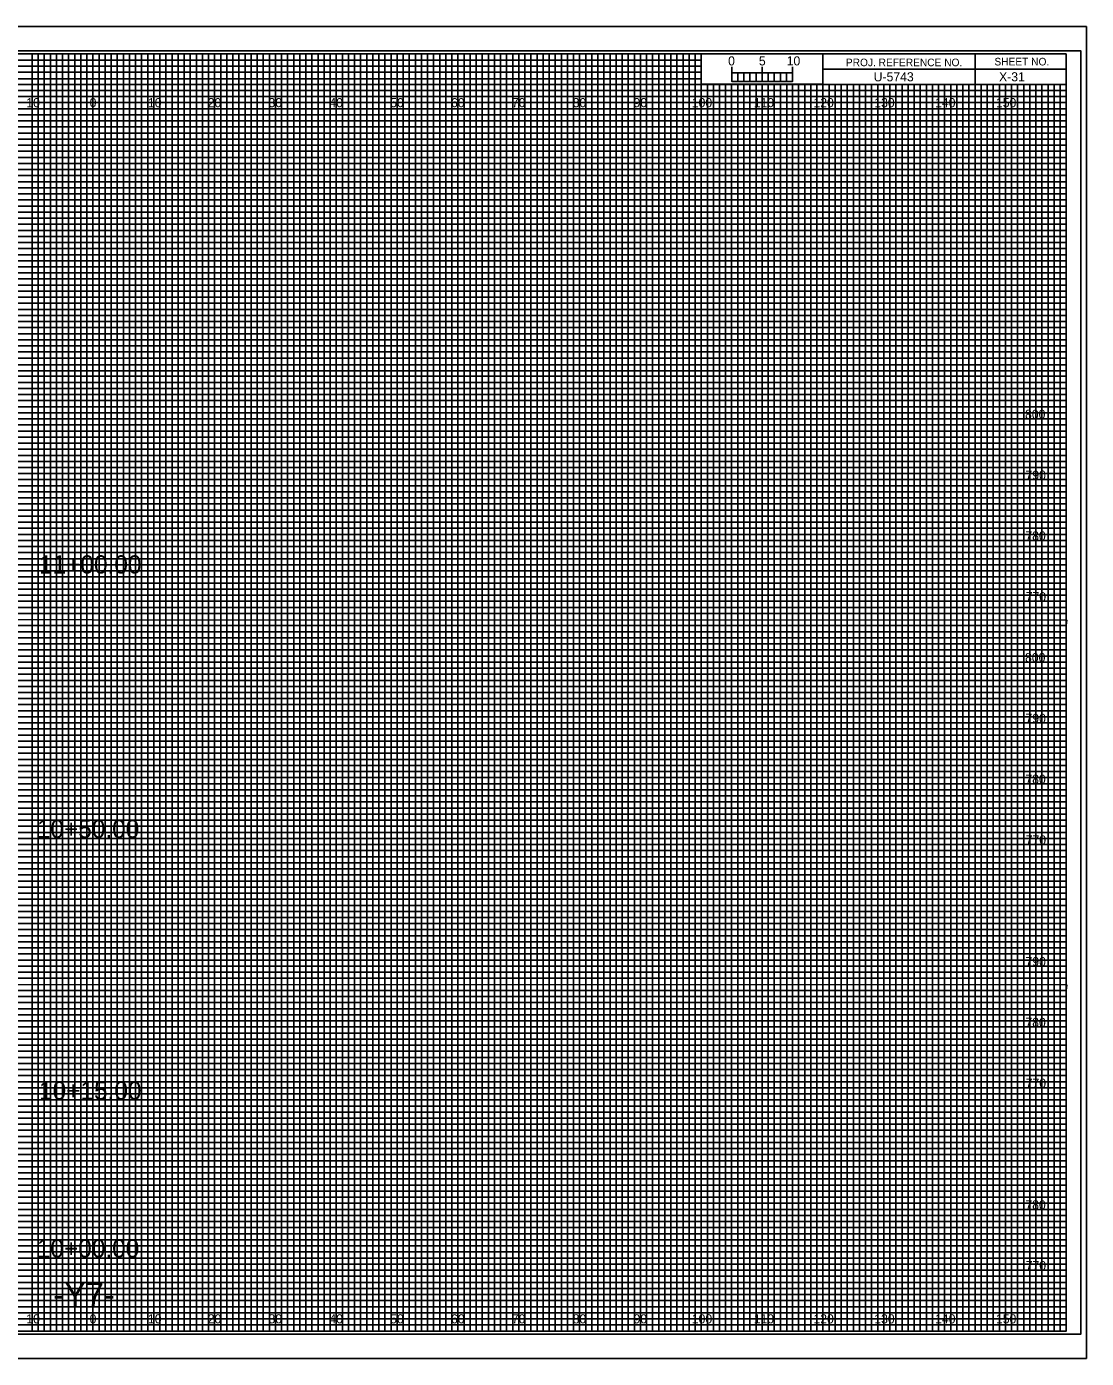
# Model space of a CAD drawing. Extents: x -13 to 323, y -4 to 214.
# Drawn here: x 149.1 to 323.3, y -4.5 to 214.5 of the extents above; entities that cross this region are included whole.
import ezdxf

# ---------------------------------------------------------------- set-up
doc = ezdxf.new("R2010")
doc.units = 0
for name, color, linetype in [('Exist Cross Section Cell', 7, 'Continuous'), ('Exist XS Center Line Elevation Label', 7, 'Continuous'), ('Exist XS Ground Line', 7, 'Continuous'), ('Prop CMT Conc Surface', 7, 'Continuous'), ('Prop CMT Concrete Structures', 7, 'Continuous'), ('Prop CMT Pvmt Course 1', 7, 'Continuous'), ('Prop CMT Pvmt Course 1 CG', 7, 'Continuous'), ('Prop CMT Pvmt Course 2', 7, 'Continuous'), ('Prop CMT Pvmt Course 3', 7, 'Continuous'), ('Prop CMT Pvmt Surface', 7, 'Continuous'), ('Prop CMT Slope Grass', 7, 'Continuous'), ('Prop CMT Subgrade Earthwork', 7, 'Continuous'), ('Prop XS Hydro Elevations', 7, 'Continuous'), ('Prop XS SE Text', 7, 'Continuous'), ('Prop XS Side Slope Text', 7, 'Continuous'), ('Scratch_Level_1', 7, 'Continuous'), ('Scratch_Level_7', 7, 'Continuous')]:
    doc.layers.add(name, color=color, linetype=linetype)

msp = doc.modelspace()

# ---------------------------------------------------------------- linework, layer by layer
at = {"layer": 'Exist XS Center Line Elevation Label'}
for points in [[(145, 0), (155, 0), (155, 210), (165, 210), (165, 0), (175, 0), (175, 210), (185, 210), (185, 0), (195, 0), (195, 210), (205, 210), (205, 0), (215, 0), (215, 210), (225, 210), (225, 0), (235, 0), (235, 210), (245, 210), (245, 0), (255, 0), (255, 210), (259.93, 210), (260, 210), (260, 205), (264.99, 205), (264.99, 0), (275, 0), (275, 205), (285, 205), (285, 0), (295, 0), (295, 205), (305, 205), (305, 0), (315, 0), (315, 205)], [(0, 205), (275, 205)], [(0, 185), (320, 185), (320, 195), (0, 195)], [(0, 165), (320, 165), (320, 175), (0, 175)], [(0, 145), (320, 145), (320, 155), (0, 155)], [(0, 125), (320, 125), (320, 135), (0, 135)], [(0, 105), (320, 105), (320, 115), (0, 115)], [(0, 85), (320, 85), (320, 95), (0, 95)], [(0, 65), (320, 65), (320, 75), (0, 75)], [(0, 45), (320, 45), (320, 55), (0, 55)], [(0, 25), (320, 25), (320, 35), (0, 35)], [(0, 5), (320, 5), (320, 15), (0, 15)]]:
    msp.add_lwpolyline(points, dxfattribs=at)
at = {"layer": 'Exist XS Ground Line'}
for p, q in [((150, 210), (140, 210)), ((150, 0), (150, 210)), ((170, 210), (160, 210)), ((160, 210), (160, 0)), ((170, 0), (170, 210)), ((190, 210), (180, 210)), ((180, 210), (180, 0)), ((190, 0), (190, 210)), ((210, 210), (200, 210)), ((200, 210), (200, 0)), ((210, 0), (210, 210)), ((230, 210), (220, 210)), ((220, 210), (220, 0)), ((230, 0), (230, 210)), ((250, 210), (240, 210)), ((240, 210), (240, 0)), ((250, 0), (250, 210)), ((260, 210), (260, 0)), ((270, 0), (270, 205)), ((290, 205), (280, 205)), ((280, 205), (280, 0)), ((290, 0), (290, 205)), ((310, 205), (300, 205)), ((300, 205), (300, 0)), ((310, 0), (310, 205)), ((160, 0), (150, 0)), ((180, 0), (170, 0)), ((200, 0), (190, 0)), ((220, 0), (210, 0)), ((240, 0), (230, 0)), ((260, 0), (250, 0)), ((280, 0), (270, 0)), ((300, 0), (290, 0)), ((320, 0), (310, 0)), ((320, 0), (320, 0))]:
    msp.add_line(p, q, dxfattribs=at)
for points in [[(0, 200), (320, 200), (320, 190), (0, 190)], [(0, 180), (320, 180), (320, 170), (0, 170)], [(0, 160), (320, 160), (320, 150), (0, 150)], [(0, 140), (320, 140), (320, 130), (0, 130)], [(0, 120), (320, 120), (320, 110), (0, 110)], [(0, 100), (320, 100), (320, 90), (0, 90)], [(0, 80), (320, 80), (320, 70), (0, 70)], [(0, 60), (320, 60), (320, 50), (0, 50)], [(0, 40), (320, 40), (320, 30), (0, 30)], [(0, 20), (320, 20), (320, 10), (0, 10)]]:
    msp.add_lwpolyline(points, dxfattribs=at)
at = {"layer": 'Prop CMT Concrete Structures'}
msp.add_lwpolyline([(-13.4, -4.5), (323.3, -4.5), (323.3, 214.5), (-13.4, 214.5)], close=True, dxfattribs=at)
at = {"layer": 'Prop CMT Pvmt Course 1'}
for p, q in [((323.3, 214.5), (-13.4, 214.5)), ((-13.4, -4.5), (323.3, -4.5))]:
    msp.add_line(p, q, dxfattribs=at)
at = {"layer": 'Prop CMT Pvmt Course 1 CG'}
for p, q in [((150, 0), (150, 210)), ((160, 0), (160, 210)), ((170, 0), (170, 210)), ((180, 0), (180, 210)), ((190, 0), (190, 210)), ((200, 0), (200, 210)), ((210, 0), (210, 210)), ((220, 0), (220, 210)), ((230, 0), (230, 210)), ((240, 0), (240, 210)), ((250, 0), (250, 210)), ((260, 0), (260, 204.69)), ((270, 0), (270, 204.69)), ((280, 0), (280, 204.69)), ((290, 0), (290, 204.69)), ((300, 0), (300, 204.69)), ((310, 0), (310, 204.69)), ((0, 200), (320, 200)), ((0, 190), (320, 190)), ((0, 180), (320, 180)), ((0, 170), (320, 170)), ((0, 160), (320, 160)), ((0, 150), (320, 150)), ((0, 140), (320, 140)), ((0, 130), (320, 130)), ((0, 120), (320, 120)), ((0, 110), (320, 110)), ((0, 100), (320, 100)), ((0, 90), (320, 90)), ((0, 80), (320, 80)), ((0, 70), (320, 70)), ((0, 60), (320, 60)), ((0, 50), (320, 50)), ((0, 40), (320, 40)), ((0, 30), (320, 30)), ((0, 20), (320, 20)), ((0, 10), (320, 10))]:
    msp.add_line(p, q, dxfattribs=at)
at = {"layer": 'Prop CMT Pvmt Course 2'}
for p, q in [((267, 205), (266.01, 205)), ((266.01, 205), (266.01, 0)), ((267, 0), (267, 205)), ((269, 205), (268, 205)), ((268, 205), (268, 0)), ((269, 0), (269, 205)), ((266.01, 0), (265, 0)), ((268, 0), (267, 0))]:
    msp.add_line(p, q, dxfattribs=at)
for points in [[(150, 0), (151, 0), (151, 210), (152, 210), (152, 0)], [(152, 0), (153, 0), (153, 210), (154, 210), (154, 0)], [(155, 0), (156, 0), (156, 210), (157, 210), (157, 0)], [(157, 0), (158, 0), (158, 210), (159, 210), (159, 0)], [(160, 0), (161, 0), (161, 210), (162, 210), (162, 0)], [(162, 0), (163, 0), (163, 210), (164, 210), (164, 0)], [(165, 0), (166, 0), (166, 210), (167, 210), (167, 0)], [(167, 0), (168, 0), (168, 210), (169, 210), (169, 0)], [(170, 0), (171, 0), (171, 210), (172, 210), (172, 0)], [(172, 0), (173, 0), (173, 210), (174, 210), (174, 0)], [(175, 0), (176, 0), (176, 210), (177, 210), (177, 0)], [(177, 0), (178, 0), (178, 210), (179, 210), (179, 0)], [(180, 0), (181, 0), (181, 210), (182, 210), (182, 0)], [(182, 0), (183, 0), (183, 210), (184, 210), (184, 0)], [(185, 0), (186, 0), (186, 210), (187, 210), (187, 0)], [(187, 0), (188, 0), (188, 210), (189, 210), (189, 0)], [(190, 0), (191, 0), (191, 210), (192, 210), (192, 0)], [(192, 0), (193, 0), (193, 210), (194, 210), (194, 0)], [(195, 0), (196, 0), (196, 210), (197, 210), (197, 0)], [(197, 0), (198, 0), (198, 210), (199, 210), (199, 0)], [(200, 0), (201, 0), (201, 210), (202, 210), (202, 0)], [(202, 0), (203, 0), (203, 210), (204, 210), (204, 0)], [(205, 0), (206, 0), (206, 210), (207, 210), (207, 0)], [(207, 0), (208, 0), (208, 210), (209, 210), (209, 0)], [(210, 0), (211, 0), (211, 210), (212, 210), (212, 0)], [(212, 0), (213, 0), (213, 210), (214, 210), (214, 0)], [(215, 0), (216, 0), (216, 210), (217, 210), (217, 0)], [(217, 0), (218, 0), (218, 210), (219, 210), (219, 0)], [(220, 0), (221, 0), (221, 210), (222, 210), (222, 0)], [(222, 0), (223, 0), (223, 210), (224, 210), (224, 0)], [(225, 0), (226, 0), (226, 210), (227, 210), (227, 0)], [(227, 0), (228, 0), (228, 210), (229, 210), (229, 0)], [(230, 0), (231, 0), (231, 210), (232, 210), (232, 0)], [(232, 0), (233, 0), (233, 210), (234, 210), (234, 0)], [(235, 0), (236, 0), (236, 210), (237, 210), (237, 0)], [(237, 0), (238, 0), (238, 210), (239, 210), (239, 0)], [(240, 0), (241, 0), (241, 210), (242, 210), (242, 0)], [(242, 0), (243, 0), (243, 210), (244, 210), (244, 0)], [(245, 0), (246, 0), (246, 210), (247, 210), (247, 0)], [(247, 0), (248, 0), (248, 210), (249, 210), (249, 0)], [(250, 0), (251, 0), (251, 210), (252, 210), (252, 0)], [(252, 0), (253, 0), (253, 210), (254, 210), (254, 0)], [(255, 0), (256, 0), (256, 210), (257, 210), (257, 0)], [(257, 0), (258, 0), (258, 210), (259, 210), (259, 0)], [(260, 0), (261, 0), (261, 205), (262.02, 205), (262.02, 0)], [(262, 0), (263, 0), (263, 205), (263.99, 205), (263.99, 0)], [(270, 0), (270.98, 0), (270.98, 205), (272, 205), (272, 0)], [(272, 0), (273, 0), (273, 205), (274.05, 205), (274.05, 0)], [(275, 0), (276, 0), (276, 205), (277, 205), (277, 0)], [(277, 0), (278, 0), (278, 205), (279, 205), (279, 0)], [(280, 0), (281, 0), (281, 205), (282, 205), (282, 0)], [(282, 0), (283, 0), (283, 205), (284, 205), (284, 0)], [(285, 0), (286, 0), (286, 205), (287, 205), (287, 0)], [(287, 0), (288, 0), (288, 205), (289, 205), (289, 0)], [(290, 0), (291, 0), (291, 205), (292, 205), (292, 0)], [(292, 0), (293, 0), (293, 205), (294, 205), (294, 0)], [(295, 0), (296, 0), (296, 205), (297, 205), (297, 0)], [(297, 0), (298, 0), (298, 205), (299, 205), (299, 0)], [(300, 0), (301, 0), (301, 205), (302, 205), (302, 0)], [(302, 0), (303, 0), (303, 205), (304, 205), (304, 0)], [(305, 0), (306, 0), (306, 205), (307, 205), (307, 0)], [(307, 0), (308, 0), (308, 205), (309, 205), (309, 0)], [(310, 0), (311, 0), (311, 205), (312, 205), (312, 0)], [(312, 0), (313, 0), (313, 205), (314, 205), (314, 0)], [(315, 0), (316, 0), (316, 205), (317, 205), (317, 0)], [(317, 0), (318, 0), (318, 205), (319, 205), (319, 0)]]:
    msp.add_lwpolyline(points, dxfattribs=at)
at = {"layer": 'Prop CMT Pvmt Course 3'}
for p, q in [((265, 205.49), (265, 207.9)), ((265, 206.9), (265, 207.9)), ((270, 205.49), (270, 207.9)), ((275, 205.49), (275, 207.9)), ((275, 206.9), (275, 207.9))]:
    msp.add_line(p, q, dxfattribs=at)
for points in [[(275, 206.9), (265, 206.9), (265, 205.49), (275, 205.49)], [(265, 206.9), (266, 206.9), (266, 205.49), (265, 205.49)], [(267, 206.9), (268, 206.9), (268, 205.49), (267, 205.49)], [(269, 206.9), (270, 206.9), (270, 205.49), (269, 205.49)], [(271, 206.9), (272, 206.9), (272, 205.49), (271, 205.49)], [(273, 206.9), (274, 206.9), (274, 205.49), (273, 205.49)]]:
    msp.add_lwpolyline(points, close=True, dxfattribs=at)
at = {"layer": 'Prop CMT Pvmt Surface'}
msp.add_lwpolyline([(-10.8, -0.5), (322.4, -0.5), (322.4, 210.5), (-10.8, 210.5)], close=True, dxfattribs=at)
at = {"layer": 'Scratch_Level_1'}
for p, q in [((0, 209), (260, 209)), ((260, 209), (260, 207.98)), ((260, 207.98), (0, 207.98)), ((0, 207), (260, 207)), ((260, 205.89), (0, 205.89)), ((260, 207), (260, 205.89)), ((0, 204), (320, 204))]:
    msp.add_line(p, q, dxfattribs=at)
for points in [[(0, 203), (270, 203), (320, 203), (320, 202), (0, 202)], [(0, 201), (320, 201), (320, 199), (0, 199)], [(0, 198), (320, 198), (320, 197), (0, 196.98)], [(0, 196), (320, 196), (320, 194), (0, 194)], [(0, 193), (320, 193), (320, 192), (0, 192)], [(0, 191), (320, 191), (320, 189), (0, 189)], [(0, 188), (320, 188), (320, 187), (0, 187)], [(0, 186), (320, 186), (320, 184), (0, 184)], [(0, 183), (320, 183), (320, 182), (0, 182)], [(0, 181), (320, 181), (320, 179), (0, 179)], [(0, 178), (320, 178), (320, 177), (0, 177)], [(0, 176), (320, 176), (320, 173.95), (320, 173), (320, 172), (0, 172)], [(0, 174), (320, 174), (320, 173), (0, 173)], [(0, 171), (320, 171), (320, 169), (0, 169.03)], [(0, 169.03), (320, 169), (320, 168), (0, 168)], [(0, 167), (320, 167), (320, 166), (0, 166)], [(0, 164), (320, 164), (320, 163), (0, 163)], [(0, 162), (320, 162), (320, 161), (0, 161)], [(-0.07, 158.89), (320, 158.89), (320, 157.88), (-0.07, 157.88)], [(0, 157), (320, 157), (320, 156), (0, 156)], [(0, 154), (320, 154), (320, 153), (0, 153)], [(0, 152), (320, 152), (320, 151), (0, 151)], [(0, 149), (320, 149), (320, 148), (0, 148)], [(0, 147), (320, 147), (320, 146), (0, 146)], [(0, 144), (320, 144), (320, 143), (0, 143)], [(0, 142), (320, 142), (320, 141), (0, 141)], [(0, 139), (320, 139), (319.99, 137.98), (0, 138)], [(0, 137), (320, 137), (320, 136), (0, 136)], [(0, 134), (320, 134), (320, 133), (0, 133)], [(0, 132), (320, 132), (320, 131), (0, 131)], [(0, 129), (320, 129), (320, 128), (0, 128)], [(0, 127), (320, 127), (320, 126), (0, 126)], [(0, 124), (320, 124), (320, 123), (0, 123)], [(0, 122), (320, 122), (320, 121), (0, 121)], [(0, 119), (320, 119), (320, 118), (0, 118)], [(0, 116.99), (320.07, 116.91), (320, 116), (0, 116)], [(0, 114), (320, 114), (320, 113), (0, 113)], [(0, 112), (320, 112), (320, 111), (0, 111)], [(0, 109), (320, 109), (320, 108), (0, 108)], [(0, 107), (320, 107), (320, 106), (0, 106)], [(0, 104), (320, 104), (320, 103), (0, 103)], [(0, 102), (320, 102), (320, 101), (0, 101)], [(0, 99), (320, 99), (320, 98), (0, 98)], [(0, 97), (320, 97), (320, 96), (0, 96)], [(0, 94), (320, 94), (320, 93), (0, 93)], [(0, 92), (320, 92), (320, 91), (0, 91)], [(0, 89), (320, 89), (320, 88), (0, 88)], [(0, 87), (320, 87), (320, 86), (0, 86)], [(0, 84), (320, 84), (320, 83), (0, 83)], [(0, 82), (320, 82), (320, 81), (0, 81)], [(0, 79), (320, 79), (319.99, 77.98), (0, 78)], [(0, 77), (320, 77), (320, 76), (0, 76)], [(0, 74), (320, 74), (320, 73), (0, 73)], [(0, 72), (320, 72), (320, 71), (0, 71)], [(0, 69), (320, 69), (320, 68), (0, 68)], [(0, 67), (320, 67), (320, 66), (0, 66)], [(0, 64), (320, 64), (320, 63), (0, 63)], [(0, 62), (320, 62), (320, 61), (0, 61)], [(0, 59), (320, 59), (320, 58), (0, 58)], [(0, 56.99), (320.07, 56.91), (320, 56), (0, 56)], [(0, 54), (320, 54), (320, 53), (0, 53)], [(0, 52), (320, 52), (320, 51), (0, 51)], [(0, 49), (320, 49), (320, 48), (0, 48)], [(0, 47), (320, 47), (320, 46), (0, 46)], [(0, 44), (320, 44), (320, 43), (0, 43)], [(0, 42), (320, 42), (320, 41), (0, 41)], [(0, 39), (320, 39), (320, 38), (0, 38)], [(0, 37), (320, 37), (320, 36), (0, 36)], [(0, 34), (320, 34), (320, 33), (0, 33)], [(0, 32), (320, 32), (320, 31), (0, 31)], [(0, 29), (320, 29), (320, 28), (0, 28)], [(0, 27), (320, 27), (320, 26), (0, 26)], [(0, 24), (320, 24), (320, 23), (0, 23)], [(0, 22), (320, 22), (320, 21), (0, 21)], [(0, 19), (320, 19), (320, 18), (0, 18)], [(0, 17), (320, 17), (320, 16), (0, 16)], [(0, 14), (320, 14), (320, 13), (0, 13)], [(0, 12), (320, 12), (320, 11), (0, 11)], [(0, 9), (320, 9), (320, 8), (0, 8)], [(0, 7), (320, 7), (320, 6), (0, 6)], [(0, 4), (320, 4), (320, 3), (0, 3)], [(0, 2), (320, 2), (320, 1), (0, 1)]]:
    msp.add_lwpolyline(points, dxfattribs=at)
at = {"layer": 'Scratch_Level_7'}
for p, q in [((305, 210), (305, 205)), ((305, 205), (305, 210)), ((280, 207.5), (280, 205)), ((320, 207.49), (280, 207.49)), ((280, 205), (320, 205))]:
    msp.add_line(p, q, dxfattribs=at)
for points in [[(320, 210), (0, 210), (0, 0), (320, 0)], [(280, 210), (260, 210), (260, 205.03), (280, 205.03)], [(320, 210), (280, 210), (280, 205), (320, 205)]]:
    msp.add_lwpolyline(points, close=True, dxfattribs=at)

# ---------------------------------------------------------------- texts
at = {"layer": 'Exist Cross Section Cell'}
for s, p in [('10', (149.04, 201.25)), ('0', (159.45, 201.25)), ('0', (159.45, 201.25)), ('10', (169.04, 201.25)), ('20', (178.86, 201.25)), ('30', (188.86, 201.25)), ('40', (198.86, 201.25)), ('50', (208.86, 201.25)), ('60', (218.86, 201.25)), ('70', (228.86, 201.25)), ('80', (238.86, 201.25)), ('90', (248.86, 201.25)), ('100', (258.44, 201.25)), ('110', (268.62, 201.25)), ('120', (278.44, 201.25)), ('130', (288.44, 201.25)), ('140', (298.44, 201.25)), ('150', (308.44, 201.25)), ('10', (149.04, 1.25)), ('0', (159.45, 1.25)), ('0', (159.45, 1.25)), ('10', (169.04, 1.25)), ('20', (178.86, 1.25)), ('30', (188.86, 1.25)), ('40', (198.86, 1.25)), ('50', (208.86, 1.25)), ('60', (218.86, 1.25)), ('70', (228.86, 1.25)), ('80', (238.86, 1.25)), ('90', (248.86, 1.25)), ('100', (258.44, 1.25)), ('110', (268.62, 1.25)), ('120', (278.44, 1.25)), ('130', (288.44, 1.25)), ('140', (298.44, 1.25)), ('150', (308.44, 1.25))]:
    msp.add_text(s, height=1.5, dxfattribs=at).set_placement(p)
at = {"layer": 'Prop CMT Conc Surface'}
for s, p in [('800', (313.22, 150)), ('790', (313.3, 140)), ('780', (313.28, 130)), ('770', (313.33, 120)), ('800', (313.22, 110)), ('790', (313.3, 100)), ('780', (313.28, 90)), ('770', (313.33, 80)), ('790', (313.3, 60)), ('780', (313.28, 50)), ('770', (313.33, 40)), ('780', (313.28, 20)), ('770', (313.33, 10))]:
    msp.add_text(s, height=1.5, dxfattribs=at).set_placement(p)
at = {"layer": 'Prop CMT Pvmt Course 3'}
msp.add_text('0', height=1.5, dxfattribs=at).set_placement((264.41, 208.12))
at = {"layer": 'Prop CMT Slope Grass'}
msp.add_text('X-31', height=1.5, dxfattribs=at).set_placement((308.95, 205.5))
at = {"layer": 'Prop CMT Subgrade Earthwork'}
for s, p in [('11+00.00', (151.13, 124.56)), ('10+50.00', (150.77, 81.08)), ('10+15.00', (151.13, 38.05)), ('10+00.00', (150.77, 12.09))]:
    msp.add_text(s, height=3, dxfattribs=at).set_placement(p)
at = {"layer": 'Prop XS Hydro Elevations'}
for s, p in [('5', (269.47, 208.12)), ('10', (274.04, 208.12))]:
    msp.add_text(s, height=1.5, dxfattribs=at).set_placement(p)
at = {"layer": 'Prop XS SE Text'}
msp.add_text('-Y7-', height=4, dxfattribs=at).set_placement((153.49, 4))
at = {"layer": 'Prop XS Side Slope Text'}
msp.add_text('U-5743', height=1.5, dxfattribs=at).set_placement((288.34, 205.5))
at = {"layer": 'Scratch_Level_7'}
for s, p in [('PROJ. REFERENCE NO.', (283.77, 207.99)), ('SHEET NO.', (308.19, 208.12))]:
    msp.add_text(s, height=1.25, dxfattribs=at).set_placement(p)

doc.saveas('drawing.dxf')
